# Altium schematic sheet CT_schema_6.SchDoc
size 278 x 170 mm
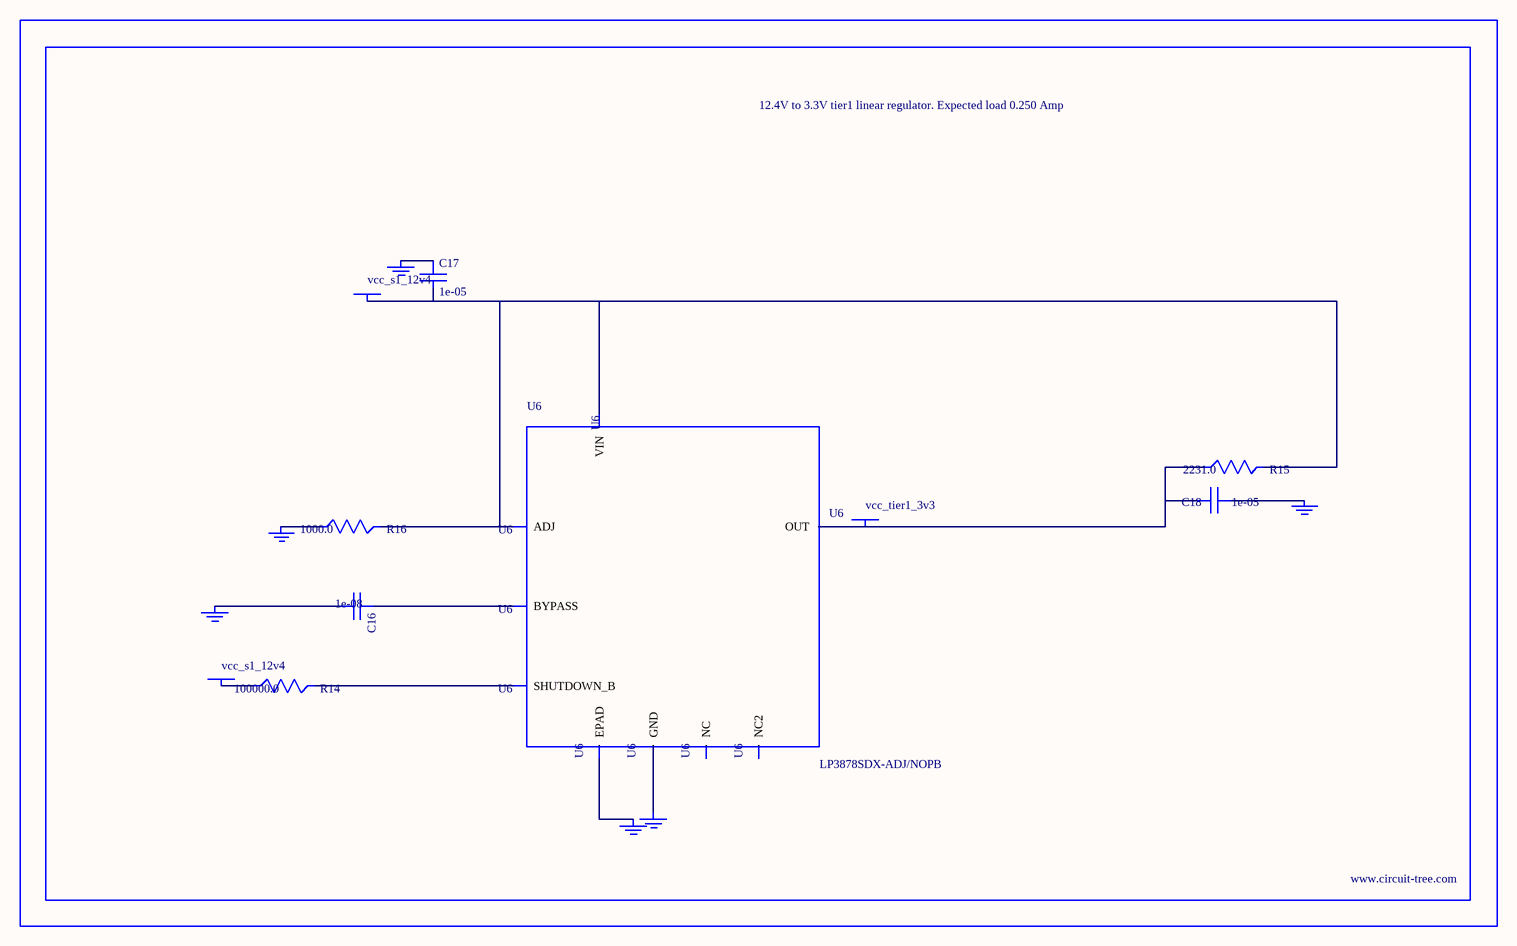
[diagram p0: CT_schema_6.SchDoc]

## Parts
BORDER5  (no value)
C16  1e-08  [C0402]
C17  1e-05  [C1210]
C18  1e-05  [C1210]
GND_INSTANCE_5_0  (no value)
GND_INSTANCE_5_1  (no value)
GND_INSTANCE_5_2  (no value)
GND_INSTANCE_5_3  (no value)
GND_INSTANCE_5_4  (no value)
GND_INSTANCE_5_5  (no value)
POWER_INSTANCE_5_0  vcc_s1_12v4
POWER_INSTANCE_5_1  vcc_s1_12v4
POWER_INSTANCE_5_2  vcc_tier1_3v3
R14  100000.0  [R0603]
R15  2231.0  [R0603]
R16  1000.0  [R0603]
U6  LP3878SDX-ADJ/NOPB  [WSON-8]

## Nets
NetC16_1: C16.1 U6.1(BYPASS)
NetC16_2: C16.2 GND_INSTANCE_5_0.0(GND)
NetC17_1: C17.1 GND_INSTANCE_5_1.0(GND)
NetC17_2: C17.2 POWER_INSTANCE_5_0.0(PWR) R15.2 R16.2 U6.4(VIN) U6.6(ADJ)
NetC18_1: C18.1 GND_INSTANCE_5_2.0(GND)
NetC18_2: C18.2 POWER_INSTANCE_5_2.0(PWR) R15.1 U6.5(OUT)
NetGND_INSTANCE_5_3_0: GND_INSTANCE_5_3.0(GND) R16.1
NetGND_INSTANCE_5_4_0: GND_INSTANCE_5_4.0(GND) U6.PAD(EPAD)
NetGND_INSTANCE_5_5_0: GND_INSTANCE_5_5.0(GND) U6.3(GND)
NetPOWER_INSTANCE_5_1_0: POWER_INSTANCE_5_1.0(PWR) R14.1
NetR14_2: R14.2 U6.8(SHUTDOWN_B)

Not connected (* = marked no-connect by the designer): U6 2(NC) 7(NC2)

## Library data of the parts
BORDER5 = BORDER_PAGE5
C16 = C0402C103K3RAC
C17 = C1210C106K5PACTU
C18 = GRM32DR61E106MA12L
GND_INSTANCE_5_0-GND_INSTANCE_5_5 = GND
POWER_INSTANCE_5_0-POWER_INSTANCE_5_2 = PWR
R14 = RC0603JR-07100KL
R15 = R15
R16 = RC0603JR-071KL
